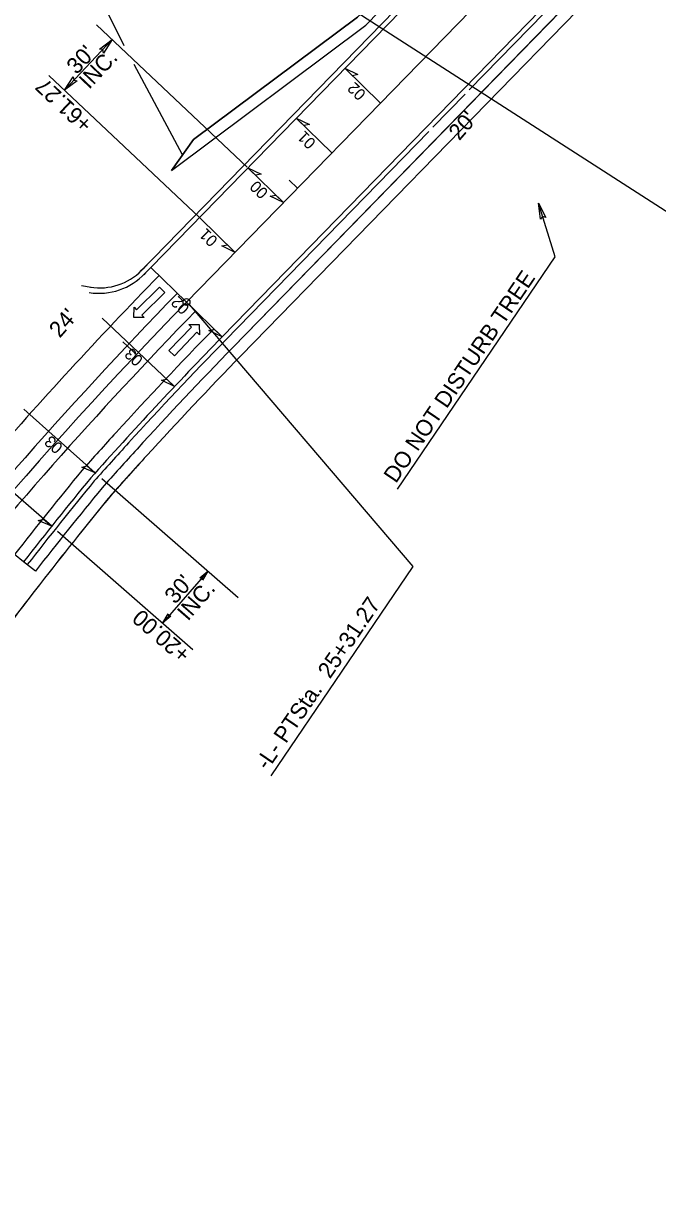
# Model space of a CAD drawing. Extents: x 1974386 to 1979988, y 776712 to 784860.
# Drawn here: x 1976496 to 1976770, y 779315 to 779824 of the extents above; entities that cross this region are included whole.
import ezdxf

# ---------------------------------------------------------------- set-up
doc = ezdxf.new("R2010")
doc.units = 0
for name, color, linetype in [('Prop Conc 2ft 6in Curb and Gutter', 7, 'Continuous'), ('Prop Conc 4in Sidewalk', 7, 'Continuous'), ('Prop Conc Drive Drop Type', 7, 'Continuous'), ('Prop Dimension', 7, 'Continuous'), ('Prop Dimension Text', 7, 'Continuous'), ('Prop DSN Text', 7, 'Continuous'), ('Prop EOT', 7, 'Continuous'), ('Prop Horizontal Alignment', 7, 'Continuous'), ('Prop Horizontal Alignment Station Label', 7, 'Continuous'), ('Prop Horizontal Alignment Tick Large', 7, 'Continuous'), ('Prop Horizontal Alignment Tick Small', 7, 'Continuous'), ('Prop Lane Arrow CELL', 7, 'Continuous'), ('Prop Lane Lines', 7, 'Continuous'), ('Prop Superelevation  Arrow CELL', 7, 'Continuous'), ('Prop Superelevation Label', 7, 'Continuous'), ('Prop Terminator CELL', 7, 'Continuous'), ('Sheet Layout Plan Border', 7, 'Continuous')]:
    doc.layers.add(name, color=color, linetype=linetype)

msp = doc.modelspace()

# ---------------------------------------------------------------- linework, layer by layer
at = {"layer": 'Prop Conc 2ft 6in Curb and Gutter'}
for p, q in [((1976688.32, 779795.62), (1977006.57, 780122.2)), ((1976546.47, 779717.4), (1976765.69, 779942.36)), ((1976583.04, 779687.6), (1976670.87, 779777.72)), ((1976520.92, 779711.14), (1976525.02, 779710.45))]:
    msp.add_line(p, q, dxfattribs=at)
for centre, radius, start, end in [((1976528.86, 779735.15), 25, 260.4237, 315.8498), ((1977926.94, 778377.94), 1923.5, 135.73946, 135.84984), ((1977926.94, 778377.94), 1876.5, 135.73946, 137.60087), ((1977926.94, 778377.94), 1876.5, 137.60087, 138.28391), ((1977976.01, 778435.99), 1876.03, 140.59771, 142.01273)]:
    msp.add_arc(centre, radius, start, end, dxfattribs=at)
at = {"layer": 'Prop Conc 4in Sidewalk'}
for p, q in [((1976586.27, 779684.45), (1977009.79, 780119.06)), ((1977009.79, 780119.06), (1976586.27, 779684.45)), ((1976589.85, 779680.96), (1977013.37, 780115.57)), ((1976589.85, 779680.96), (1977013.37, 780115.57)), ((1976569.28, 779774.25), (1976559.67, 779760.84)), ((1976559.67, 779760.84), (1976569.28, 779774.25)), ((1976533.32, 779620.32), (1976533.59, 779620.63)), ((1976500.96, 779587.88), (1976495.85, 779591.9))]:
    msp.add_line(p, q, dxfattribs=at)
for points in [[(1976569.28, 779774.25), (1976640.03, 779827.02), (1976758.88, 779948.99)], [(1976758.88, 779948.98), (1976640.03, 779827.02), (1976569.28, 779774.25)], [(1976559.67, 779760.84), (1976643.63, 779823.56), (1976762.46, 779945.49)], [(1976559.67, 779760.84), (1976643.63, 779823.56), (1976762.46, 779945.49)], [(1976500.96, 779587.88), (1976495.85, 779591.9), (1976491.91, 779594.98)]]:
    msp.add_lwpolyline(points, dxfattribs=at)
for centre, radius, start, end in [((1977926.94, 778377.94), 1872, 135.73946, 137.58605), ((1977926.94, 778377.94), 1872, 135.73946, 137.58605), ((1977926.94, 778377.94), 1867, 135.73946, 137.56744), ((1977926.94, 778377.94), 1867, 135.73946, 137.56744), ((1977926.94, 778377.94), 1872, 137.58605, 138.27742), ((1977926.94, 778377.94), 1872, 137.58605, 138.27742), ((1977926.94, 778377.94), 1867, 137.56744, 138.28391), ((1977926.94, 778377.94), 1867, 137.56744, 138.2743), ((1977976.01, 778435.99), 1871.53, 140.6042, 142.01325), ((1977976.01, 778435.99), 1871.53, 140.6042, 142.01325), ((1977976.01, 778435.99), 1866.53, 140.6042, 142.01244), ((1977976.01, 778435.99), 1866.53, 140.60732, 142.01244), ((1977926.94, 778377.94), 1867, 138.2743, 138.28391), ((1977976.01, 778435.99), 1866.53, 140.6042, 140.60732), ((1977976.01, 778435.99), 1866.53, 142.01244, 143.82111), ((1977976.36, 778436.41), 1866.55, 142.02902, 143.82111)]:
    msp.add_arc(centre, radius, start, end, dxfattribs=at)
at = {"layer": 'Prop Conc Drive Drop Type'}
msp.add_line((1976686.57, 779793.83), (1976672.61, 779779.51), dxfattribs=at)
at = {"layer": 'Prop Dimension'}
for p, q in [((1976527.39, 779823.63), (1976592.35, 779762.3)), ((1976513.51, 779795.48), (1976534.1, 779817.3)), ((1976506.8, 779801.82), (1976571.75, 779740.49)), ((1976614.18, 779753.22), (1976614.18, 779753.22)), ((1976529.59, 779627.89), (1976588.53, 779576.43)), ((1976510.53, 779605.09), (1976568.99, 779554.05)), ((1976575.45, 779587.85), (1976555.91, 779565.47))]:
    msp.add_line(p, q, dxfattribs=at)
at = {"layer": 'Prop DSN Text'}
for p, q in [((1976539.33, 779814.7), (1976515.35, 779862.91)), ((1976564.48, 779767.54), (1976543.63, 779806.62)), ((1976725.37, 779723.6), (1976718.17, 779746.64)), ((1976657.28, 779623.23), (1976725.37, 779723.6))]:
    msp.add_line(p, q, dxfattribs=at)
at = {"layer": 'Prop EOT'}
for p, q in [((1976581.61, 779688.99), (1977005.14, 780123.59)), ((1976550.82, 779719), (1976767.11, 779940.96))]:
    msp.add_line(p, q, dxfattribs=at)
for centre, radius, start, end in [((1977926.94, 778377.94), 1921.5, 135.73946, 135.87087), ((1976528.39, 779735.12), 27.32, 261.1736, 316.5998), ((1977926.94, 778377.94), 1878.5, 135.73946, 138.28391), ((1977976.01, 778435.99), 1878.03, 140.59771, 142.01251)]:
    msp.add_arc(centre, radius, start, end, dxfattribs=at)
at = {"layer": 'Prop Horizontal Alignment'}
msp.add_line((1976566.21, 779704), (1976989.74, 780138.6), dxfattribs=at)
msp.add_arc((1977926.94, 778377.94), 1900, 135.73946, 152.1381, dxfattribs=at)
at = {"layer": 'Prop Horizontal Alignment Station Label'}
for p, q in [((1976567.29, 779702.95), (1976663.93, 779589.8)), ((1976663.93, 779589.8), (1976602.63, 779499.46))]:
    msp.add_line(p, q, dxfattribs=at)
msp.add_circle((1976566.21, 779704), 1.5, dxfattribs=at)
at = {"layer": 'Prop Horizontal Alignment Tick Large'}
msp.add_line((1976544.58, 779681.43), (1976538.76, 779686.91), dxfattribs=at)
at = {"layer": 'Prop Horizontal Alignment Tick Small'}
msp.add_line((1976614.18, 779753.22), (1976610.6, 779756.71), dxfattribs=at)
at = {"layer": 'Prop Lane Arrow CELL'}
for p, q in [((1976544.58, 779700.72), (1976554.6, 779710.5)), ((1976556.9, 779708.14), (1976546.89, 779698.36)), ((1976554.6, 779710.5), (1976556.9, 779708.14)), ((1976543.51, 779697.31), (1976543.53, 779701.8)), ((1976543.53, 779701.8), (1976544.58, 779700.72)), ((1976547.93, 779697.29), (1976543.51, 779697.31)), ((1976546.89, 779698.36), (1976547.93, 779697.29)), ((1976558.6, 779683.16), (1976568.31, 779693.24)), ((1976570.69, 779690.95), (1976560.97, 779680.87)), ((1976567.23, 779694.28), (1976571.65, 779694.4)), ((1976568.31, 779693.24), (1976567.23, 779694.28)), ((1976571.77, 779689.91), (1976570.69, 779690.95)), ((1976571.65, 779694.4), (1976571.77, 779689.91)), ((1976560.97, 779680.87), (1976558.6, 779683.16)), ((1976663.93, 779589.8), (1976663.93, 779589.8))]:
    msp.add_line(p, q, dxfattribs=at)
at = {"layer": 'Prop Lane Lines'}
for centre, radius, start, end in [((1977926.94, 778377.94), 1916.5, 135.73946, 139.08605), ((1977926.94, 778377.94), 1905.5, 135.73946, 141.94983), ((1977926.94, 778377.94), 1894.5, 135.73946, 141.23948), ((1977926.94, 778377.94), 1883.5, 135.73946, 137.61142), ((1977926.94, 778377.94), 1883.5, 137.61142, 138.28391), ((1977976.01, 778435.99), 1883.03, 140.59771, 142.01248)]:
    msp.add_arc(centre, radius, start, end, dxfattribs=at)
at = {"layer": 'Prop Superelevation  Arrow CELL'}
for p, q in [((1976649.96, 779789.94), (1976634.57, 779804.94)), ((1976629.03, 779768.45), (1976613.63, 779783.46)), ((1976608.09, 779746.97), (1976592.69, 779761.97)), ((1976587.15, 779725.48), (1976571.75, 779740.49)), ((1976581.61, 779688.99), (1976550.82, 779719)), ((1976561.08, 779667.59), (1976529.82, 779697.11)), ((1976510.76, 779644.6), (1976495.94, 779657.85)), ((1976526.78, 779630.27), (1976510.76, 779644.6)), ((1976508, 779607.3), (1976477.7, 779633.55))]:
    msp.add_line(p, q, dxfattribs=at)
for points in [[(1976634.57, 779804.94), (1976640.26, 779802.19), (1976637.88, 779801.71)], [(1976613.63, 779783.46), (1976619.32, 779780.7), (1976616.94, 779780.23)], [(1976592.69, 779761.97), (1976598.38, 779759.22), (1976596, 779758.74)], [(1976608.09, 779746.97), (1976602.4, 779749.72), (1976604.78, 779750.19)], [(1976587.15, 779725.48), (1976581.46, 779728.24), (1976583.84, 779728.71)], [(1976581.61, 779688.99), (1976575.92, 779691.75), (1976578.3, 779692.22)], [(1976561.08, 779667.59), (1976555.35, 779670.25), (1976557.72, 779670.76)], [(1976526.78, 779630.27), (1976520.98, 779632.78), (1976523.34, 779633.35)], [(1976508, 779607.3), (1976502.16, 779609.71), (1976504.51, 779610.33)]]:
    msp.add_lwpolyline(points, close=True, dxfattribs=at)
at = {"layer": 'Prop Terminator CELL'}
for points in [[(1976528.62, 779813.19), (1976534.1, 779817.3), (1976530.31, 779811.54), (1976530.03, 779812.99)], [(1976518.98, 779799.59), (1976513.51, 779795.48), (1976517.29, 779801.24), (1976517.57, 779799.79)], [(1976719.07, 779739.85), (1976718.17, 779746.64), (1976721.34, 779740.52), (1976719.94, 779740.98)], [(1976571.91, 779584.97), (1976575.45, 779587.85), (1976573.08, 779583.91), (1976572.86, 779584.87)], [(1976559.46, 779568.35), (1976555.91, 779565.47), (1976558.29, 779569.4), (1976558.51, 779568.44)]]:
    msp.add_lwpolyline(points, close=True, dxfattribs=at)
at = {"layer": 'Sheet Layout Plan Border'}
msp.add_lwpolyline([(1977111.11, 779526.05), (1977868.38, 780703.57), (1976985.24, 781271.52), (1976227.97, 780094)], close=True, dxfattribs=at)

# ---------------------------------------------------------------- texts
at = {"layer": 'Prop Dimension'}
for s, p in [("30'", (1976518.79, 779801.92)), ('INC.', (1976524.14, 779795.57))]:
    msp.add_text(s, height=7, rotation=46.644, dxfattribs=at).set_placement(p)
at = {"layer": 'Prop Dimension Text'}
for s, rotation, p in [('+61.27', 136.644, (1976526.15, 779781.55)), ("20'", 48.955, (1976684.03, 779773.4)), ("24'", 48.955, (1976511.46, 779688.19)), ("30'", 48.955, (1976561.35, 779573.25)), ('INC.', 48.955, (1976566.81, 779566.01)), ('+20.00', 138.955, (1976568.52, 779552.89))]:
    msp.add_text(s, height=7, rotation=rotation, dxfattribs=at).set_placement(p)
at = {"layer": 'Prop DSN Text'}
msp.add_text('DO NOT DISTURB TREE', height=7, rotation=55.8441, dxfattribs=at).set_placement((1976656.66, 779625.44))
at = {"layer": 'Prop Horizontal Alignment Station Label'}
msp.add_text('-L- PTSta.  25+31.27', height=7, rotation=55.7257, dxfattribs=at).set_placement((1976601.22, 779501.52))
at = {"layer": 'Prop Superelevation Label'}
for s, rotation, p in [('02', 135.7395, (1976644.07, 779794.19)), ('01', 135.7395, (1976622.44, 779773.15)), ('00', 135.7395, (1976601.86, 779751.67)), ('01', 135.7395, (1976580.04, 779731.01)), ('02', 135.7395, (1976567.86, 779701.76)), ('03', 136.644, (1976547.8, 779679.48)), ('03', 138.1901, (1976513.18, 779641.79))]:
    msp.add_text(s, height=5, rotation=rotation, dxfattribs=at).set_placement(p)

doc.saveas('drawing.dxf')
